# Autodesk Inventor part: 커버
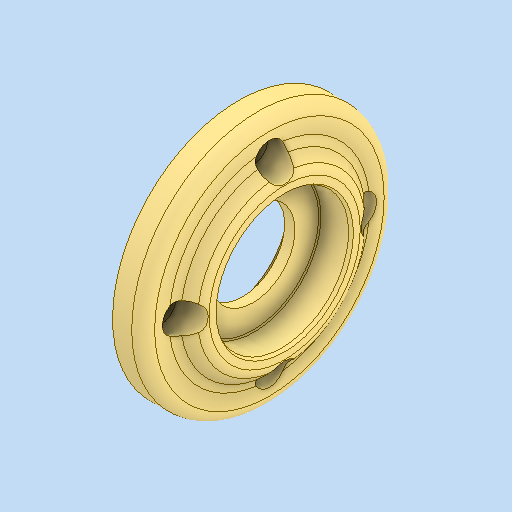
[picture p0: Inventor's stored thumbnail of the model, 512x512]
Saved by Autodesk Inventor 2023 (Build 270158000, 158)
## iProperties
Created: 2026-06
Part Number: 커버
Material: 알루미늄 6061
Document SubType Name: Modeling
Designer: home
Density: 2.7 g/cm^3
Appearance: 기본값
Author: jhkim
Sending System: Autodesk Inventor 2027
Preprocessor: ST-DEVELOPER v20.1
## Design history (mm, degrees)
feature "솔리드1"
node "솔리드2"
